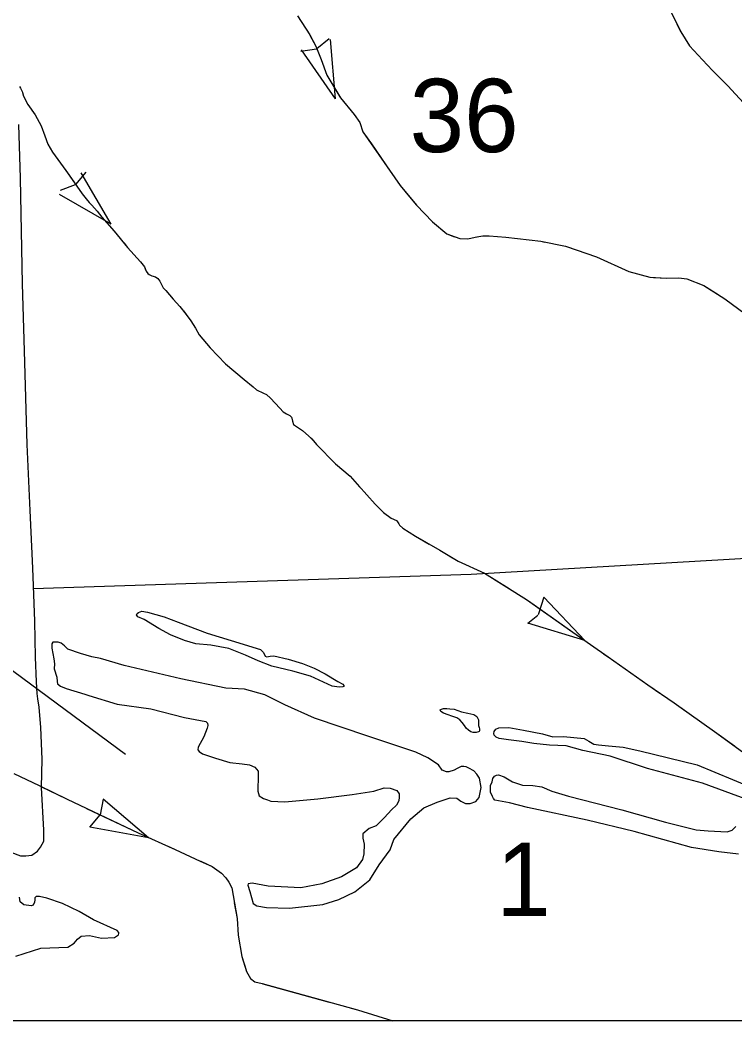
# Model space of a CAD drawing. Extents: x -117616 to 64730, y 54117 to 789866.
# Drawn here: x 63422.6 to 63505, y 54389.3 to 54504.7 of the extents above; entities that cross this region are included whole.
import ezdxf

# ---------------------------------------------------------------- set-up
doc = ezdxf.new("R2010")
doc.units = 0
for name, color, linetype in [('35', 7, 'Continuous'), ('43', 7, 'Continuous'), ('46', 7, 'Continuous'), ('47', 7, 'Continuous'), ('5', 7, 'Continuous'), ('7', 7, 'Continuous'), ('R_No Plot', 7, 'Continuous')]:
    doc.layers.add(name, color=color, linetype=linetype)

msp = doc.modelspace()

# ---------------------------------------------------------------- linework, layer by layer
at = {"layer": '35'}
for points in [[(63455.13, 54430.51), (63456.47, 54429.97), (63457.76, 54429.31), (63459.22, 54428.43), (63459.79, 54428.11), (63459.89, 54427.96), (63459.88, 54427.86), (63459.79, 54427.8), (63459.34, 54427.78), (63458.54, 54427.9), (63456.07, 54429.04), (63454, 54429.6), (63451.58, 54430.18), (63450.02, 54430.8), (63448.56, 54431.46), (63446.62, 54432.21), (63444.55, 54432.61), (63442.84, 54432.78), (63441.52, 54433.15), (63439.92, 54433.78), (63438.55, 54434.53), (63436.86, 54435.55), (63436.13, 54435.88), (63436.01, 54436.09), (63436.07, 54436.26), (63436.22, 54436.38), (63436.59, 54436.51), (63437.28, 54436.41), (63439.2, 54435.87), (63440.79, 54435.24), (63444.14, 54433.98), (63446.9, 54433.14), (63450.27, 54432.12), (63450.62, 54431.76), (63450.84, 54431.35), (63451.02, 54431.28), (63451.41, 54431.34), (63451.83, 54431.38), (63453.49, 54431.01), (63455.13, 54430.51)], [(63430.83, 54431.27), (63429.53, 54431.64), (63428.07, 54432.15), (63427.71, 54432.52), (63427.31, 54432.82), (63426.98, 54432.96), (63426.54, 54432.96), (63426.36, 54432.96), (63426.25, 54432.77), (63426.22, 54432.26), (63426.47, 54431.05), (63426.55, 54430.47), (63426.52, 54429.9), (63426.8, 54428.93), (63426.84, 54428.42), (63426.87, 54428.16), (63427.22, 54427.89), (63427.88, 54427.61), (63430.02, 54426.98)], [(63434.58, 54430.28), (63431.85, 54431.06), (63430.83, 54431.27)], [(63474.3, 54418.45), (63474.01, 54418.6), (63473.72, 54418.62), (63473.43, 54418.62), (63472.97, 54418.4), (63472.61, 54418.2), (63472.01, 54418), (63471.74, 54418), (63471.23, 54418.2), (63470.79, 54418.8), (63469.56, 54419.62), (63468.18, 54420.29), (63462.65, 54422.14), (63456.51, 54424.21), (63453.08, 54425.72), (63450.77, 54426.88), (63448.44, 54427.53), (63446.3, 54427.66), (63441.12, 54428.71), (63434.58, 54430.28)], [(63430.02, 54426.98), (63430.5, 54426.82), (63433.77, 54425.82), (63437.64, 54425.29), (63441.53, 54424.29), (63443.97, 54423.83), (63444.18, 54423.61), (63444.21, 54423.35), (63444.16, 54423.05), (63443.77, 54422.04), (63443.12, 54420.86), (63443.08, 54420.56), (63443.2, 54420.35), (63443.61, 54420.1), (63445.1, 54419.57), (63446.77, 54419.07), (63448.19, 54418.94), (63449.02, 54418.81), (63449.65, 54418.54), (63450.03, 54418.08), (63450.03, 54417.62), (63449.97, 54415.78), (63450.14, 54415.25), (63450.65, 54414.95), (63451.11, 54414.77), (63451.48, 54414.62), (63453.11, 54414.57), (63456.89, 54414.9), (63460.86, 54415.39), (63463.37, 54415.78), (63464.55, 54416.16), (63465.23, 54416.11), (63466.02, 54415.85), (63466.29, 54415.47), (63466.29, 54415.08), (63466.22, 54414.66), (63465.98, 54414.18), (63465.39, 54413.63), (63464.57, 54412.73), (63463.61, 54411.8), (63462.8, 54411.47), (63462.07, 54410.86), (63462.07, 54410.37), (63462.25, 54409.69), (63462.22, 54408.57), (63462.03, 54407.91), (63461.36, 54406.96), (63459.64, 54405.91), (63457.35, 54405.09), (63454.93, 54404.65), (63451.17, 54404.85), (63449.33, 54405.18), (63448.86, 54405.09), (63448.84, 54404.96), (63449.06, 54404.22), (63449.46, 54402.84), (63449.88, 54402.55), (63450.97, 54402.38), (63453.62, 54402.31), (63457.49, 54402.73), (63459.33, 54403.29), (63461.18, 54404.18), (63462.91, 54405.58), (63463.98, 54407.29), (63465.25, 54409.01), (63465.67, 54410.23), (63467.63, 54412.59), (63469.12, 54413.86), (63470.65, 54414.53), (63472.16, 54415.02), (63472.92, 54414.97), (63473.37, 54414.62), (63473.92, 54414.37), (63474.45, 54414.37), (63475.1, 54414.59), (63475.48, 54415.06), (63475.72, 54416.2), (63475.54, 54417.29), (63475.23, 54417.73), (63474.9, 54418.11), (63474.3, 54418.45)], [(63472.6, 54425.23), (63473.46, 54424.92), (63474.19, 54424.79), (63474.9, 54424.61), (63475.22, 54424.37), (63475.42, 54424), (63475.42, 54423.63), (63475.41, 54423.34), (63475.49, 54423.12), (63475.52, 54422.96), (63475.53, 54422.73), (63475.49, 54422.67), (63475.42, 54422.62), (63475.16, 54422.54), (63474.8, 54422.54), (63474.52, 54422.62), (63474.25, 54422.8), (63473.98, 54423.06), (63473.82, 54423.36), (63473.54, 54423.71), (63473.26, 54423.99), (63472.92, 54424.22), (63472.35, 54424.41), (63471.92, 54424.57), (63471.4, 54424.79), (63471.08, 54424.98), (63471.02, 54425.14), (63471.15, 54425.25), (63471.38, 54425.31), (63471.77, 54425.3), (63472.13, 54425.26), (63472.6, 54425.23)], [(63480.41, 54421.5), (63478.89, 54421.71), (63477.79, 54421.85), (63477.44, 54422), (63477.21, 54422.23), (63477.19, 54422.44), (63477.23, 54422.67), (63477.4, 54422.92), (63477.78, 54423.09), (63478.93, 54423.13), (63480.61, 54422.83), (63482.79, 54422.4), (63483.99, 54422.05), (63485.2, 54422.1), (63487.61, 54421.85), (63488.12, 54421.53), (63488.72, 54421.2), (63489.25, 54421.13), (63490.39, 54421), (63492.1, 54420.84), (63494.02, 54420.42), (63500.62, 54418.82), (63504.7, 54417.12)], [(63504.7, 54417.12), (63507.28, 54416.07), (63508.79, 54415.35), (63509.27, 54415.03), (63509.53, 54414.8), (63509.78, 54414.48), (63509.78, 54414.28), (63509.76, 54414.09), (63509.62, 54413.93), (63509.36, 54413.82), (63508.74, 54413.91), (63506.47, 54414.8), (63501.24, 54416.71), (63494.9, 54418.41), (63490.58, 54419.83), (63487.43, 54420.47), (63485.53, 54420.99), (63483.6, 54421.09), (63481.8, 54421.29), (63480.41, 54421.5)], [(63505.41, 54408.53), (63503.14, 54408.8), (63499.99, 54409.28), (63493.35, 54411.12), (63487.95, 54412.43), (63481.07, 54413.91), (63478.99, 54414.45), (63477.72, 54414.65), (63477.32, 54414.76), (63477.13, 54414.95), (63477.05, 54415.17), (63476.82, 54415.67), (63476.82, 54416.07), (63476.82, 54416.45), (63476.99, 54416.86), (63477.07, 54417.24), (63477.26, 54417.51), (63477.49, 54417.63), (63477.72, 54417.67), (63478.38, 54417.44), (63479.34, 54416.84), (63480.51, 54416.47), (63481.68, 54416.45), (63482.72, 54416.3), (63483.89, 54415.8), (63485.8, 54415.22), (63491.93, 54413.65), (63496.97, 54412.2), (63500.53, 54411.32), (63501.91, 54411.2), (63504.08, 54411.1), (63504.66, 54411.28), (63504.85, 54411.47), (63505.08, 54411.72)]]:
    msp.add_lwpolyline(points, dxfattribs=at)
at = {"layer": '43'}
for p, q in [((63458.22, 54502.47), (63456.78, 54501.34)), ((63458.94, 54495.57), (63458.36, 54502.41)), ((63454.95, 54501.07), (63456.76, 54501.33)), ((63458.94, 54495.57), (63455.02, 54501.21)), ((63430.16, 54487.1), (63428.98, 54485.7)), ((63433.06, 54481.11), (63429.63, 54487.06)), ((63427.24, 54485.06), (63428.96, 54485.69)), ((63433.06, 54481.11), (63427.12, 54484.55)), ((63482.97, 54438.15), (63482.28, 54436.1)), ((63487.67, 54433.14), (63482.97, 54438.15)), ((63481.1, 54435.13), (63482.27, 54436.07)), ((63487.67, 54433.14), (63481.1, 54435.13)), ((63432.15, 54414.86), (63431.82, 54413.06)), ((63437.38, 54410.42), (63432.15, 54414.86)), ((63430.63, 54411.65), (63431.81, 54413.04)), ((63437.38, 54410.42), (63430.63, 54411.65))]:
    msp.add_line(p, q, dxfattribs=at)
for points in [[(63497.31, 54506.18), (63498.74, 54503.29)], [(63454.57, 54505.13), (63455.96, 54502.93), (63456.65, 54501.63), (63457.3, 54500.12), (63457.95, 54498.31), (63459.52, 54495.67), (63461.09, 54493.77), (63461.75, 54492.85), (63462.1, 54491.78), (63466.4, 54485.58), (63468.27, 54483.32), (63470.13, 54481.39), (63471.77, 54480), (63473.25, 54479.47), (63474.2, 54479.44), (63475.03, 54479.61), (63475.92, 54479.79), (63476.66, 54479.79), (63478.58, 54479.61), (63482.59, 54479.17), (63485.46, 54478.6), (63489.02, 54477.36), (63492.75, 54475.67), (63495.19, 54475.01), (63497.14, 54474.9), (63498.51, 54474.93), (63499.42, 54474.81), (63501.41, 54474.07), (63503.81, 54472.52), (63508.35, 54469.17)], [(63498.3, 54504.17), (63498.74, 54503.29), (63499.73, 54501.66), (63501.23, 54500.07), (63502.38, 54498.84), (63503.21, 54498.02)], [(63455.98, 54502.91), (63456.65, 54501.63), (63457.3, 54500.12), (63457.95, 54498.31), (63459.44, 54495.81)], [(63498.74, 54503.29), (63499.73, 54501.66), (63501.23, 54500.07), (63502.38, 54498.84), (63504.17, 54497.06), (63506.39, 54494.64)], [(63422.52, 54496.98), (63422.64, 54496.81), (63422.84, 54496.32), (63422.96, 54495.86), (63423.47, 54494.91), (63424.33, 54493.73), (63424.99, 54492.44), (63425.43, 54491.31), (63425.77, 54490.34), (63426.33, 54489.43), (63427.84, 54487.31), (63429.72, 54484.62), (63430.2, 54484.06), (63430.55, 54483.63), (63430.86, 54483.32), (63431.46, 54482.61), (63431.99, 54481.95), (63433.43, 54480.32), (63434.97, 54478.44), (63436.46, 54476.77), (63436.9, 54476.21), (63437.12, 54475.7), (63437.32, 54475.43), (63437.46, 54475.31), (63437.78, 54475.16), (63438.2, 54475.06), (63438.46, 54474.87), (63438.68, 54474.57), (63439.05, 54473.77), (63439.37, 54473.47), (63440.22, 54472.5), (63441, 54471.62), (63441.71, 54470.71), (63442.25, 54470), (63442.79, 54469.15), (63443.2, 54468.37), (63444.5, 54466.88), (63446.25, 54465.04), (63448.4, 54463.21), (63449.43, 54462.38), (63449.84, 54462.04), (63450.65, 54461.65), (63450.99, 54461.48), (63451.43, 54461.09), (63452.53, 54459.91), (63452.92, 54459.5), (63453.29, 54459.25), (63453.68, 54459.08), (63453.85, 54458.89), (63453.9, 54458.76), (63453.99, 54458.42), (63454.09, 54458.03), (63455.13, 54457.36), (63456.19, 54456.37), (63456.73, 54455.73), (63458.93, 54453.51), (63460.61, 54452.07), (63463.51, 54448.87), (63464.48, 54447.9), (63465.37, 54447.24), (63465.96, 54446.96), (63466.1, 54446.81), (63466.25, 54446.59), (63466.3, 54446.42), (63466.71, 54446.11), (63468.16, 54445.18), (63470.96, 54443.54), (63473.08, 54442.3), (63476.11, 54440.9), (63480.95, 54437.89), (63486.3, 54434.11), (63490.35, 54431.25), (63494.94, 54428.05), (63497.97, 54425.97), (63502.63, 54422.67), (63505.86, 54420.32)], [(63422.84, 54496.3), (63422.96, 54495.86), (63423.47, 54494.91), (63424.33, 54493.73), (63424.99, 54492.44), (63425.43, 54491.31), (63425.77, 54490.34), (63426.33, 54489.43), (63426.43, 54489.29)], [(63461.1, 54493.76), (63461.75, 54492.85), (63462.1, 54491.78), (63463.08, 54490.37)], [(63463.08, 54490.37), (63465.33, 54487.11)], [(63427.96, 54487.14), (63429.72, 54484.62), (63430.2, 54484.06), (63430.55, 54483.63), (63430.86, 54483.32), (63431.46, 54482.61), (63431.99, 54481.95), (63432.88, 54480.95)], [(63466.89, 54484.98), (63468.27, 54483.32), (63470.13, 54481.39), (63471.77, 54480), (63472.64, 54479.68)], [(63475.22, 54479.65), (63475.92, 54479.79), (63476.66, 54479.79), (63478.58, 54479.61), (63482.59, 54479.17), (63483.08, 54479.07)], [(63434.57, 54478.92), (63434.97, 54478.44), (63436.46, 54476.77), (63436.9, 54476.21), (63437.05, 54475.86)], [(63485.67, 54478.53), (63489.02, 54477.36), (63492.75, 54475.67), (63493.01, 54475.6)], [(63437.05, 54475.86), (63437.12, 54475.7), (63437.32, 54475.43), (63437.46, 54475.31), (63437.78, 54475.16), (63438.2, 54475.06), (63438.46, 54474.87), (63438.68, 54474.57), (63439.05, 54473.77), (63439.37, 54473.47), (63439.68, 54473.12)], [(63495.58, 54474.99), (63497.14, 54474.9), (63498.51, 54474.93), (63499.42, 54474.81), (63501.41, 54474.07), (63503.04, 54473.02)], [(63441.4, 54471.12), (63441.71, 54470.71), (63442.25, 54470), (63442.79, 54469.15), (63443.2, 54468.37), (63444.5, 54466.88), (63446.25, 54465.04), (63446.34, 54464.97)], [(63448.35, 54463.26), (63448.4, 54463.21), (63449.43, 54462.38), (63449.84, 54462.04), (63450.65, 54461.65), (63450.99, 54461.48), (63451.43, 54461.09), (63452.53, 54459.91), (63452.92, 54459.5), (63453.29, 54459.25), (63453.68, 54459.08), (63453.85, 54458.89), (63453.9, 54458.76), (63453.99, 54458.42), (63454.07, 54458.1)], [(63456.1, 54456.45), (63456.19, 54456.37), (63456.73, 54455.73), (63458.93, 54453.51), (63460.61, 54452.07), (63461.7, 54450.86)], [(63463.47, 54448.91), (63463.51, 54448.87), (63464.48, 54447.9), (63465.37, 54447.24), (63465.96, 54446.96), (63466.1, 54446.81), (63466.25, 54446.59), (63466.3, 54446.42), (63466.71, 54446.11), (63468.16, 54445.18), (63469.75, 54444.24)], [(63472.03, 54442.91), (63473.08, 54442.3), (63476.11, 54440.9), (63478.97, 54439.12)], [(63481.2, 54437.71), (63484.44, 54435.43)], [(63412.8, 54436.24), (63434.73, 54420.04)], [(63484.44, 54435.43), (63486.3, 54434.11), (63487.67, 54433.14)], [(63489.83, 54431.62), (63490.35, 54431.25), (63494.94, 54428.05), (63496.33, 54427.09)], [(63498.5, 54425.59), (63502.63, 54422.67), (63504.94, 54420.99)], [(63421.84, 54417.8), (63424.76, 54416.42), (63428, 54414.86), (63436.2, 54410.98), (63440.46, 54409.06), (63443.34, 54407.73), (63444.7, 54407.1), (63445.78, 54406.32), (63446.29, 54405.81), (63446.65, 54405.3), (63446.98, 54404.64), (63447.58, 54401.09), (63447.73, 54399.2), (63448.12, 54396.73), (63448.69, 54394.99), (63449.14, 54394.21), (63449.65, 54393.82), (63450.49, 54393.61), (63461.48, 54390.57), (63465.53, 54389.3)], [(63425.03, 54416.29), (63427.84, 54414.93)], [(63430.22, 54413.8), (63436.2, 54410.98), (63437.39, 54410.44)], [(63439.8, 54409.35), (63440.46, 54409.06), (63443.34, 54407.73), (63443.4, 54407.71)], [(63443.4, 54407.71), (63444.7, 54407.1), (63445.78, 54406.32), (63446.29, 54405.81), (63446.56, 54405.42)], [(63447.27, 54402.91), (63447.58, 54401.09), (63447.73, 54399.2), (63448.12, 54396.73), (63448.64, 54395.14)], [(63450.56, 54393.59), (63458.2, 54391.48)], [(63460.74, 54390.78), (63461.48, 54390.57), (63465.53, 54389.3)]]:
    msp.add_lwpolyline(points, dxfattribs=at)
at = {"layer": '46'}
msp.add_lwpolyline([(63421.5, 54408.74), (63422.64, 54408.33), (63423.24, 54408.33), (63423.91, 54408.4), (63424.6, 54408.86), (63424.94, 54409.33), (63425.31, 54410.02), (63425.31, 54410.58), (63425.31, 54411.28), (63425.04, 54416.22), (63425.11, 54419.48), (63424.96, 54423.13), (63424.78, 54425.48), (63424.62, 54426.41), (63424.55, 54427.02), (63424.46, 54428.38), (63424.36, 54431.23), (63424.28, 54435.39), (63424.03, 54441.5), (63423.73, 54448.14), (63423.4, 54455.73), (63423.07, 54466.54), (63422.87, 54474.26), (63422.62, 54486.42), (63422.42, 54492.63)], dxfattribs=at)
at = {"layer": '47'}
for points in [[(63431.04, 54400.95), (63429.4, 54401.92), (63427.46, 54402.85), (63425.67, 54403.45), (63424.81, 54403.63), (63424.44, 54403.63), (63424.29, 54403.48), (63424.29, 54403.26), (63424.25, 54403), (63424.07, 54402.66), (63423.84, 54402.55), (63423.02, 54402.7), (63422.58, 54403.04), (63422.5, 54403.56)], [(63422.09, 54396.77), (63424.96, 54397.7), (63428.06, 54397.81), (63428.8, 54398.26), (63429.21, 54398.74), (63429.62, 54399.08), (63430.59, 54399.15), (63431.95, 54398.84), (63433.46, 54398.92), (63433.91, 54399.23), (63433.95, 54399.38), (63433.95, 54399.49), (63433.78, 54399.73), (63431.04, 54400.95)]]:
    msp.add_lwpolyline(points, dxfattribs=at)
at = {"layer": '7'}
for p, q in [((63474.59, 54440.8), (63513.05, 54443.02)), ((63424.1, 54439.15), (63474.59, 54440.8))]:
    msp.add_line(p, q, dxfattribs=at)
at = {"layer": 'R_No Plot'}
msp.add_lwpolyline([(62347.42, 55314.94), (63854.85, 55314.94), (63854.85, 54389.3), (62347.42, 54389.3)], close=True, dxfattribs=at)

# ---------------------------------------------------------------- texts
at = {"layer": '5'}
for s, height, p in [('36', 8.448, (63467.48, 54489.43)), ('1', 8.45, (63477.47, 54401.41))]:
    msp.add_text(s, height=height, dxfattribs=at).set_placement(p)

doc.saveas('drawing.dxf')
